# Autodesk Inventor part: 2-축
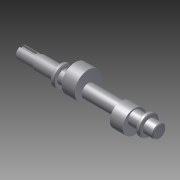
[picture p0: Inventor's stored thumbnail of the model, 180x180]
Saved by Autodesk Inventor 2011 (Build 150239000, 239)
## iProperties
Created: 2014-12
Part Number: 2-축
Document SubType Name: Modeling
Designer: user
Density: 1 g/cm^3
Author: user
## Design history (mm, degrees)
sketch "스케치1"
  geometry: L1 (-90, 0)-(90, 0); L2 (-90, 0)-(-90, 7.5); L3 (-90, 7.5)-(-66, 7.5); L4 (-66, 7.5)-(-66, 8.5); L5 (-66, 8.5)-(-39, 8.5); L6 (-39, 8.5)-(-39, 13); L7 (-39, 13)-(-34, 13); L8 (-34, 13)-(-34, 8.5); L9 (90, 8.5)-(90, 0); L10 (72, 13)-(72, 8.5); L11 (72, 13)-(77, 13); L12 (77, 13)-(77, 8.5); L13 (-34, 8.5)-(72, 8.5); L14 (77, 8.5)-(90, 8.5); 2 further points
  constraints: 28 end point, 8 parallel, 7 perpendicular, 1 coincident, 1 horizontal, 1 midpoint
  dimensions: "d0" = 180 distance of L1.start L1.end; "d2" = 17 diameter of L5 L1; "d3" = 24 distance of L2.end L3.end; "d4" = 27 distance of L4.end L5.end; "d5" = 26 diameter of L7 L1; "d6" = 5 distance of L6.end L7.end; "d13" = 15 diameter of L3 L1; "d17" = 13 distance between parallel lines of L9 L12; "d18" = 5 distance of L10.start L11.end; "d19" = 17 diameter of L14 L1; "d20" = 26 diameter of L11 L1; "d22" = 17 diameter of L13 L1
revolve "회전1" sketch "스케치1" stored, may be unused: angle "d23" = 90 deg
node "작업 평면1"
sketch "스케치2"
  geometry: C1 r 8.5 at (0, 0) reference; C2 r 17.5 at (0, 6); 1 further point
  constraints: 1 centre point, 1 vertical alignment
  dimensions: "d25" = 35 diameter of C2; "d26" = 6 distance of point (0, 0) C2.centre
extrude "돌출1" join sketch "스케치2" distance "d27" = 17; taper "d28" = 0 deg
node "작업 평면2"
sketch "스케치3"
  geometry: C1 r 8.5 at (0, 0) reference; C2 r 15 at (0, -5); 1 further point
  constraints: 1 centre point
  dimensions: "d30" = 5 distance of point (0, 0) C2.centre; "d31" = 30 diameter of C2
extrude "돌출2" join sketch "스케치3" distance "d32" = 17; taper "d33" = 0 deg
chamfer "모따기1" distance "d34" = 1; stored, may be unused: second distance "d35" = 2, angle "d36" = 45 deg
node "작업 평면3"
sketch "스케치4"
  geometry: L1 (-12, 0)-(12, 0) reference; L2 (12, -4)-(12, 0) reference; L3 (39, -4)-(12, -4) reference; L4 (39, -9.367)-(39, -4) reference; L5 (43, -10.618)-(40, -10.618) reference; L6 (44, -4)-(44, -9.367) reference; L7 (58.5, -4)-(44, -4) reference; L8 (58.5, -17.436)-(58.5, -4) reference; L9 (75.5, -17.436)-(58.5, -17.436) reference; L10 (75.5, -4)-(75.5, -17.436) reference; L11 (118.5, -4)-(75.5, -4) reference; L12 (118.5, -8.292)-(118.5, -4) reference; L13 (135.5, -8.292)-(118.5, -8.292) reference; L14 (135.5, -4)-(135.5, -8.292) reference; L15 (150, -4)-(135.5, -4) reference; L16 (150, -9.367)-(150, -4) reference; L17 (154, -10.618)-(151, -10.618) reference; L18 (155, -4)-(155, -9.367) reference; L19 (167, -4)-(155, -4) reference; L20 (155, 4)-(167, 4) reference; L21 (155, 9.367)-(155, 4) reference; L22 (151, 10.618)-(154, 10.618) reference; L23 (150, 4)-(150, 9.367) reference; L24 (135.5, 4)-(150, 4) reference; L25 (135.5, 8.292)-(135.5, 4) reference; L26 (118.5, 8.292)-(135.5, 8.292) reference; L27 (118.5, 4)-(118.5, 8.292) reference; L28 (75.5, 4)-(118.5, 4) reference; L29 (75.5, 17.436)-(75.5, 4) reference; L30 (58.5, 17.436)-(75.5, 17.436) reference; L31 (58.5, 4)-(58.5, 17.436) reference; L32 (44, 4)-(58.5, 4) reference; L33 (44, 9.367)-(44, 4) reference; L34 (40, 10.618)-(43, 10.618) reference; L35 (39, 4)-(39, 9.367) reference; L36 (12, 4)-(39, 4) reference; L37 (12, 0)-(12, 4) reference; L38 (5.5, 2.5)-(-17.208, 2.5); L39 (5.5, -2.5)-(-17.208, -2.5); L40 (-17.208, -2.5)-(-17.208, 2.5); L41 (-12, -7.5)-(-12, 7.5) reference; A1 r 2.5 centre (5.5, 0) between (5.5, -2.5) and (5.5, 2.5); 2 further points
  constraints: 6 end point, 2 perpendicular, 2 point on circle, 2 tangent, 1 centre point, 1 horizontal alignment, 1 parallel, 1 point on line, 10 other
  dimensions: "d37" = 5 diameter of A1; "d38" = 20 dimension on A1 L41
extrude "돌출3" cut sketch "스케치4" distance "d39" = 3; taper "d40" = 0 deg
chamfer "모따기2" distance "d41" = 1; stored, may be unused: second distance "d42" = 2, angle "d43" = 45 deg
node "솔리드1"
node "절단 모서리 투영1"
node "절단 모서리 투영2"
node "절단 모서리 투영3"
other parameters: "d8" = 17, "d24" = 14.5, "d29" = 14.5
